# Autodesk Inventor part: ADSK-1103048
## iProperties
Shininess: 54.0
Length Units: 11269
Angle Units: 11279
Time Units: 11290
Mass Units: 11286
Length Display Precision: 2
Angle Display Precision: 2
Compacted: True
Created: 2000-07
Part Number: ADSK-1103048
Document SubType Name: Modeling
Description: ENGINE SLEEVE - SIDE
Mass: 20.1156 g
Surface Area: 29.6394 cm^2
Volume: 2.5625 cm^3
Density: 7.85 g/cm^3
Material: Cast Steel
Density: 0.0
Volumn: 0.0
Area: 0.0
PropertySet Name: Model Information
Control State: 0
Master: False
Checked Out: False
Author: Autodesk, Inc.
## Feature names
1. Revolution1
2. Fillet2
3. Sweep1
4. Fillet3
5. Fillet4
6. Mirror1
7. Fillet5
8. Extrusion4
